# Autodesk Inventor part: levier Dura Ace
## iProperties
Created: 2011-11
Part Number: levier Dura Ace
Document SubType Name: Modeling
Designer: Laur
Density: 1 g/cm^3
Mass: 2.17327 g
Surface Area: 20.1795 cm^2
Volume: 2.17327 cm^3
Author: Laur
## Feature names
1. Extrusion1
2. Extrusion2
